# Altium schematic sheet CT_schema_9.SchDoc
size 147 x 119 mm
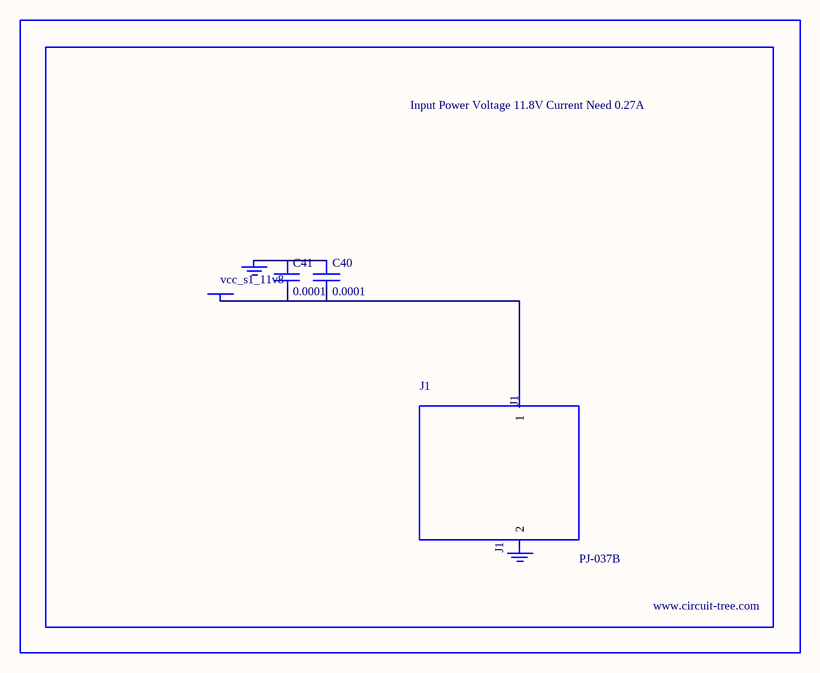
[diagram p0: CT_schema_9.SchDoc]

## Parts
BORDER8  (no value)
C40  0.0001  [EXV-9H]
C41  0.0001  [EXV-9H]
GND_INSTANCE_8_0  (no value)
GND_INSTANCE_8_1  (no value)
J1  PJ-037B  [PJ-037B_PACKAGE]
POWER_INSTANCE_8_0  vcc_s1_11v8

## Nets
NetC40_1: C40.1 C41.1 GND_INSTANCE_8_0.0(GND)
NetC40_2: C40.2 C41.2 J1.1 POWER_INSTANCE_8_0.0(PWR)

Not connected (* = marked no-connect by the designer): GND_INSTANCE_8_1 0(GND); J1 2

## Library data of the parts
BORDER8 = BORDER_PAGE8
C40 C41 = EDK107M035A9HAA
GND_INSTANCE_8_0 GND_INSTANCE_8_1 = GND
POWER_INSTANCE_8_0 = PWR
